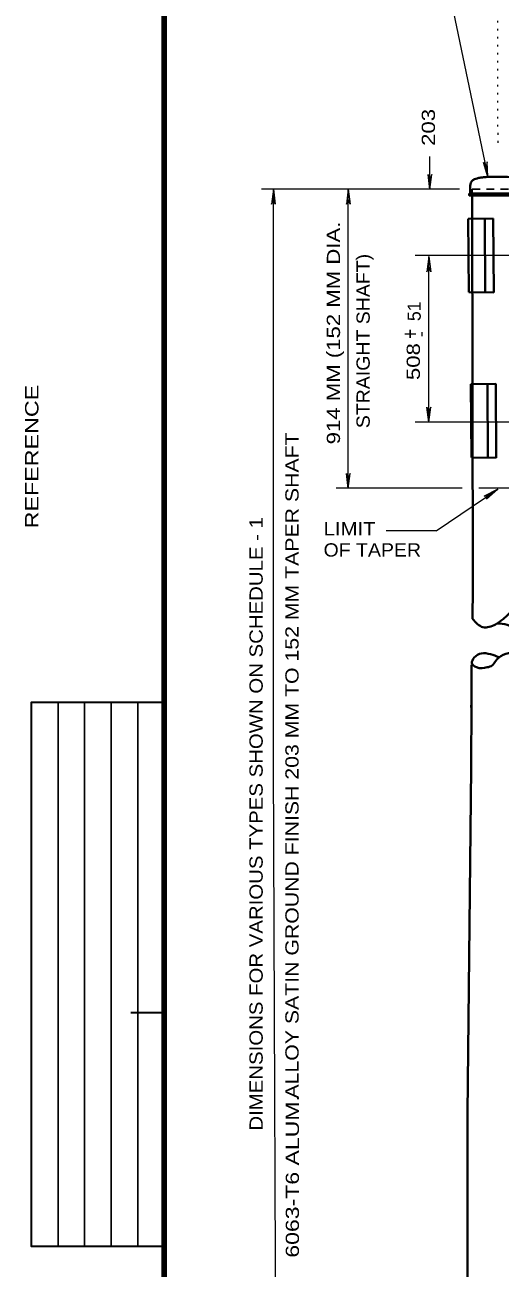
# Model space of a CAD drawing. Extents: x 312583 to 312854, y 144418 to 144597.
# Drawn here: x 312608.5 to 312635.8, y 144489.4 to 144560.7 of the extents above; entities that cross this region are included whole.
import ezdxf
from ezdxf.enums import TextEntityAlignment as Align

# ---------------------------------------------------------------- set-up
doc = ezdxf.new("R2010")
doc.units = 0
doc.header["$LTSCALE"] = 0.3
doc.linetypes.add('DOTTED', pattern=[1.5, 0.3, -1.2])
doc.linetypes.add('SHORT_DASHED', pattern=[2.7, 1.5, -1.2])
doc.layers.add('1', color=7, linetype='Continuous', lineweight=35)

msp = doc.modelspace()

# ---------------------------------------------------------------- linework, layer by layer
at = {"layer": '1', "lineweight": 158}
msp.add_line((312616.5, 144423.1446), (312616.5, 144585.0846), dxfattribs=at)
at = {"layer": '1', "linetype": 'DOTTED', "lineweight": 13}
msp.add_line((312635.6079, 144572.9396), (312635.6308, 144553.7093), dxfattribs=at)
at = {"layer": '1', "lineweight": 13}
for p, q in [((312633.0078, 144561.8986), (312635.0741, 144552.0166)), ((312631.742, 144551.4752), (312631.742, 144553.1832)), ((312635.0284, 144552.8858), (312634.975, 144552.596)), ((312635.0741, 144552.0166), (312635.0284, 144552.8858)), ((312634.8149, 144552.8477), (312634.975, 144552.596)), ((312635.0741, 144552.0166), (312634.8149, 144552.8477)), ((312631.6352, 144552.1462), (312631.742, 144551.8717)), ((312631.742, 144551.2922), (312631.6352, 144552.1462)), ((312631.8488, 144552.1462), (312631.742, 144551.8717)), ((312631.742, 144551.2922), (312631.8488, 144552.1462)), ((312633.4348, 144551.315), (312622.0811, 144551.315)), ((312622.7674, 144551.315), (312622.6606, 144550.4534)), ((312622.7674, 144551.315), (312622.8741, 144550.4534)), ((312627.0602, 144551.315), (312626.9535, 144550.4534)), ((312627.0602, 144551.315), (312627.167, 144550.4534)), ((312627.0602, 144534.1359), (312627.0602, 144551.315)), ((312622.6606, 144550.4534), (312622.7674, 144550.7279)), ((312622.8741, 144550.4534), (312622.7674, 144550.7279)), ((312626.9535, 144550.4534), (312627.0602, 144550.7279)), ((312627.167, 144550.4534), (312627.0602, 144550.7279)), ((312740.9778, 144547.5102), (312630.9044, 144547.5102)), ((312631.681, 144547.4416), (312631.5742, 144546.5799)), ((312631.681, 144537.9484), (312631.681, 144547.4416)), ((312631.681, 144547.4416), (312631.7878, 144546.5799)), ((312631.5742, 144546.5799), (312631.681, 144546.8544)), ((312631.7878, 144546.5799), (312631.681, 144546.8544)), ((312631.5742, 144538.81), (312631.681, 144538.5356)), ((312631.681, 144537.9484), (312631.5742, 144538.81)), ((312631.7878, 144538.81), (312631.681, 144538.5356)), ((312631.681, 144537.9484), (312631.7878, 144538.81)), ((312636.9651, 144537.9484), (312630.9044, 144537.9484)), ((312626.9535, 144534.9976), (312627.0602, 144534.723)), ((312627.0602, 144534.1359), (312626.9535, 144534.9976)), ((312627.167, 144534.9976), (312627.0602, 144534.723)), ((312627.0602, 144534.1359), (312627.167, 144534.9976)), ((312633.6025, 144534.1588), (312626.374, 144534.1588)), ((312632.0928, 144531.7188), (312635.6384, 144534.0978)), ((312636.5991, 144534.1588), (312634.548, 144534.1588)), ((312635.6384, 144534.0978), (312634.8606, 144533.7013)), ((312634.8606, 144533.7013), (312635.1504, 144533.7699)), ((312635.6384, 144534.0978), (312634.9826, 144533.5259)), ((312634.9826, 144533.5259), (312635.1504, 144533.7699)), ((312632.0928, 144531.7188), (312629.2258, 144531.7188))]:
    msp.add_line(p, q, dxfattribs=at)
at = {"layer": '1', "lineweight": 40}
for p, q in [((312637.2168, 144551.071), (312633.999, 144551.071)), ((312634.06, 144551.071), (312634.06, 144551.4294)), ((312634.1744, 144550.9567), (312635.6384, 144550.9567)), ((312634.1744, 144550.9567), (312634.2049, 144528.44)), ((312637.0948, 144550.9567), (312635.6384, 144550.9567)), ((312635.3715, 144549.6223), (312633.9456, 144549.607)), ((312633.9685, 144545.398), (312633.9456, 144549.607)), ((312634.9216, 144545.3828), (312634.8988, 144549.6147)), ((312635.402, 144545.3828), (312635.3715, 144549.6223)), ((312635.402, 144545.3828), (312633.9685, 144545.398)), ((312634.121, 144535.9126), (312634.0905, 144540.1216)), ((312635.0741, 144535.8973), (312635.0512, 144540.1368)), ((312635.5469, 144535.9049), (312634.121, 144535.9126)), ((312634.2049, 144528.44), (312634.1896, 144526.6634)), ((312634.1362, 144524.0328), (312634.121, 144521.8597)), ((312634.1058, 144518.1234), (312634.121, 144521.8597)), ((312634.121, 144521.8597), (312634.1134, 144521.5699)), ((312634.1058, 144518.1234), (312633.9075, 144498.2908)), ((312633.9075, 144498.2908), (312633.9075, 144477.8024))]:
    msp.add_line(p, q, dxfattribs=at)
at = {"layer": '1', "linetype": 'SHORT_DASHED', "lineweight": 25}
for q in [(312634.1744, 144550.9567), (312637.0948, 144551.315)]:
    msp.add_line((312634.1744, 144551.315), q, dxfattribs=at)
at = {"layer": '1', "lineweight": 25}
for p, q in [((312610.4087, 144490.6573), (312610.4087, 144521.8756)), ((312611.9315, 144490.6573), (312611.9315, 144521.8756)), ((312613.4543, 144490.6573), (312613.4543, 144521.8756)), ((312614.9772, 144490.6573), (312614.9772, 144521.8756))]:
    msp.add_line(p, q, dxfattribs=at)
at = {"layer": '1'}
msp.add_line((312614.58, 144504.0846), (312616.5, 144504.0846), dxfattribs=at)
msp.add_line((312614.58, 144504.0846), (312616.5, 144504.0846), dxfattribs=at)
at = {"layer": '1', "lineweight": 158}
msp.add_lwpolyline([(312849, 144423.0846), (312849, 144585.0846), (312616.5, 144585.0846), (312616.5, 144423.0846)], close=True, dxfattribs=at)
msp.add_lwpolyline([(312616.5, 144585.0846), (312616.5, 144423.0846), (312849, 144423.0846)], dxfattribs=at)
at = {"layer": '1', "lineweight": 13}
msp.add_lwpolyline([(312622.9428, 144475.431), (312622.7674, 144518.4208), (312622.7674, 144551.315)], dxfattribs=at)
at = {"layer": '1', "lineweight": 40}
for points in [[(312634.1744, 144550.9567), (312633.999, 144550.9567), (312633.999, 144551.071)], [(312635.5469, 144535.9049), (312635.524, 144540.1368), (312634.0905, 144540.1216)]]:
    msp.add_lwpolyline(points, dxfattribs=at)
at = {"layer": '1'}
msp.add_lwpolyline([(312616.5, 144490.6573), (312608.8858, 144490.6573), (312608.8858, 144521.8756), (312616.5, 144521.8756)], dxfattribs=at)
at = {"layer": '1', "lineweight": 40}
for points in [[(312635.6384, 144552.0242), (312635.2952, 144552.0242), (312634.8606, 144552.0013), (312634.6548, 144551.9784), (312634.4489, 144551.9327), (312634.304, 144551.8793), (312634.1744, 144551.7954), (312634.0829, 144551.6582), (312634.0676, 144551.5972), (312634.06, 144551.4294)], [(312635.6384, 144552.0242), (312635.9739, 144552.0242), (312636.4085, 144552.0013), (312636.6144, 144551.9784), (312636.8202, 144551.9327), (312636.9728, 144551.8793), (312637.0948, 144551.7954), (312637.1862, 144551.6582), (312637.2015, 144551.5972), (312637.2168, 144551.4294)], [(312634.1896, 144526.6634), (312634.7844, 144526.183), (312635.5088, 144526.3432), (312635.9358, 144526.6406), (312636.2865, 144526.9608), (312636.6906, 144527.281), (312637.0414, 144527.2048), (312637.0414, 144526.7702), (312636.744, 144526.2059), (312636.1798, 144526.3127), (312635.6155, 144526.3966)], [(312637.1481, 144524.4369), (312636.4085, 144524.7114), (312635.8138, 144524.5208), (312635.524, 144524.2539), (312635.3105, 144523.987), (312635.036, 144523.8803), (312634.4184, 144523.8803), (312634.1515, 144524.1167), (312634.2888, 144524.4369), (312634.6929, 144524.6809), (312635.2266, 144524.6276), (312635.707, 144524.4674)]]:
    msp.add_spline(points, degree=3, dxfattribs=at)

# ---------------------------------------------------------------- texts
at = {"layer": '1'}
for s, height, width, p in [('203 ', 0.76, 1.25, (312632.0335, 144553.7967)), ('914 MM (152 MM DIA.', 0.76, 1.25, (312626.5861, 144536.6743)), ('STRAIGHT SHAFT)', 0.76, 1.1, (312628.2911, 144537.601)), ('508 ', 0.76, 1.25, (312631.1695, 144540.36)), ('REFERENCE                                                              ', 0.7682, 1.3, (312609.2854, 144531.8549)), (' ALLOY SATIN GROUND FINISH 203 MM TO 152 MM TAPER SHAFT', 0.76, 1.2, (312624.2091, 144498.8006)), ('DIMENSIONS FOR VARIOUS TYPES SHOWN ON SCHEDULE - 1', 0.76, 1.15, (312622.1504, 144497.3036)), ('6063-T6 ALUM. ', 0.76, 1.3, (312624.2311, 144490.0121))]:
    msp.add_text(s, height=height, rotation=90, dxfattribs=dict(at, width=width)).set_placement(p)
msp.add_text('51 ', height=0.76, rotation=90, dxfattribs=at).set_placement((312631.2185, 144543.7431))
at = {"layer": '1', "width": 0.8}
msp.add_text('+', height=0.915, rotation=90, dxfattribs=at).set_placement((312631.0605, 144543.0106), align=Align.CENTER)
at = {"layer": '1'}
msp.add_text('-', height=0.76, rotation=90, dxfattribs=at).set_placement((312631.5792, 144542.9886), align=Align.CENTER)
for s, width, p in [('LIMIT', 1.15, (312625.642, 144531.4544)), ('OF TAPER', 1.1, (312625.642, 144530.2369))]:
    msp.add_text(s, height=0.76, dxfattribs=dict(at, width=width)).set_placement(p)

doc.saveas('drawing.dxf')
